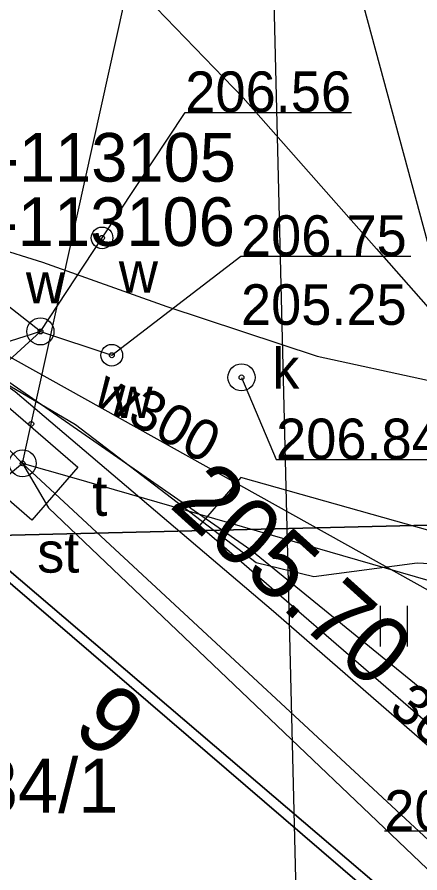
# Model space of a CAD drawing. Extents: x 6512606 to 6513347, y 6022524 to 6022728.
# Drawn here: x 6512803.1 to 6512810.55, y 6022664.12 to 6022679.94 of the extents above; entities that cross this region are included whole.
import ezdxf

# ---------------------------------------------------------------- set-up
doc = ezdxf.new("R2010")
doc.units = 0
for name, color, linetype in [('121-Punkt osnowy szczegółowej-Atr103', 7, 'Continuous'), ('211-numer działki ewidencyjnej', 7, 'Continuous'), ('216-obręb ewidencyjny', 7, 'Continuous'), ('217-kontur klasyfikacyjny', 7, 'Continuous'), ('218-kontur użytku gruntowego', 7, 'Continuous'), ('219-działka ewidencyjna', 7, 'Continuous'), ('238-Punkt adresowy budynku', 7, 'Continuous'), ('312-budynek ewidencyjny', 7, 'Continuous'), ('4', 7, 'Continuous'), ('940-Trawnik symb. poj.', 7, 'Continuous'), ('chodnik (powierzchnia)', 7, 'Continuous'), ('Default', 7, 'Continuous'), ('inna obudowa przewodu - sieć telekomunikacyjna (linia)', 7, 'Continuous'), ('komora podziemna - przewód telekomunikacyjny (powierzchnia)', 7, 'Continuous'), ('krawężnik (linia)', 7, 'Continuous'), ('Obszar opracowania', 7, 'Continuous'), ('przewód elektroenergetyczny (linia)', 7, 'Continuous'), ('przewód elektroenergetyczny (linia)-Atr1', 7, 'Continuous'), ('przewód kanalizacyjny (linia)', 7, 'Continuous'), ('przewód telekomunikacyjny (linia)', 7, 'Continuous'), ('przewód wodociągowy (linia)', 7, 'Continuous'), ('przewód wodociągowy (linia)-Atr1', 7, 'Continuous'), ('punkt o określonej wysokości (sieć kanalizacyjna)', 7, 'Continuous'), ('punkt o określonej wysokości (sieć kanalizacyjna)-Atr2', 7, 'Continuous'), ('punkt o określonej wysokości (sieć telekomunikacyjna)', 7, 'Continuous'), ('punkt o określonej wysokości (sieć telekomunikacyjna)-Atr2', 7, 'Continuous'), ('punkt o określonej wysokości (sieć wodociągowa)', 7, 'Continuous'), ('punkt o określonej wysokości (sieć wodociągowa)-Atr2', 7, 'Continuous'), ('punkt o określonej wysokości (sieć wodociągowa)-Atr3', 7, 'Continuous'), ('szafa telekomunikacyjna (punkt)-Atr17', 7, 'Continuous'), ('właz okrągły - siec kanalizacyjna (punkt)', 7, 'Continuous'), ('właz okrągły - siec kanalizacyjna (punkt)-Atr17', 7, 'Continuous'), ('właz okrągły - siec telekomunikacyjna (punkt)', 7, 'Continuous'), ('właz okrągły - siec telekomunikacyjna (punkt)-Atr17', 7, 'Continuous'), ('właz okrągły - siec wodociągowa (punkt)', 7, 'Continuous'), ('właz okrągły - siec wodociągowa (punkt)-Atr17', 7, 'Continuous'), ('zasuwa - siec wodociągowa (punkt)', 7, 'Continuous'), ('zasuwa - siec wodociągowa (punkt)-Atr17', 7, 'Continuous')]:
    doc.layers.add(name, color=color, linetype=linetype)

# ---------------------------------------------------------------- blocks, each defined once
blk = doc.blocks.new('940P')
at = {"layer": 'Default'}
for p, q in [((-2.5, -3.75), (-2.5, 3.75)), ((2.5, -3.75), (2.5, 3.75))]:
    blk.add_line(p, q, dxfattribs=at)
blk = doc.blocks.new('US22')
at = {"layer": 'Default'}
blk.add_circle((0, 0), 2.5, dxfattribs=at)
blk = doc.blocks.new('PW01')
at = {"layer": 'Default'}
blk.add_circle((0, 0), 0.45, dxfattribs=at)
blk = doc.blocks.new('US25')
at = {"layer": 'Default'}
blk.add_circle((0, 0), 2, dxfattribs=at)

msp = doc.modelspace()

# ---------------------------------------------------------------- linework, layer by layer
at = {"layer": '216-obręb ewidencyjny'}
for points in [[(6512688.62, 6022674.91), (6512702.58, 6022674.18), (6512725.78, 6022672.95), (6512730.35, 6022672.71), (6512735.76, 6022672.94), (6512745.51, 6022673.33), (6512754.87, 6022673.72), (6512768.24, 6022674.27), (6512785.56, 6022674.74), (6512790.49, 6022674.74), (6512796.96, 6022674.74), (6512801.96, 6022670.34), (6512828.67, 6022670.98), (6512833.61, 6022675.02), (6512836.69, 6022675.17), (6512851.94, 6022675.93)], [(6512836.687, 6022675.173), (6512833.61, 6022675.02), (6512828.67, 6022670.98), (6512801.96, 6022670.34), (6512810.18, 6022663.28), (6512825.37, 6022649.66), (6512838.47, 6022634.29), (6512852.25, 6022608.25), (6512853.17, 6022604.51), (6512855.78, 6022583.95), (6512858.85, 6022571.74), (6512828.23, 6022562.62), (6512818.47, 6022559.72), (6512824.714, 6022553.406)], [(6512852.25, 6022608.25), (6512838.47, 6022634.29), (6512825.37, 6022649.66), (6512810.18, 6022663.28), (6512801.96, 6022670.34), (6512796.96, 6022674.74), (6512790.49, 6022674.74), (6512785.56, 6022674.74), (6512768.24, 6022674.27), (6512754.87, 6022673.72), (6512745.51, 6022673.33), (6512735.76, 6022672.94), (6512730.35, 6022672.71), (6512725.78, 6022672.95), (6512702.575, 6022674.177)]]:
    msp.add_lwpolyline(points, dxfattribs=at)
at = {"layer": '217-kontur klasyfikacyjny'}
msp.add_lwpolyline([(6512810.18, 6022663.28), (6512801.96, 6022670.34)], dxfattribs=at)
at = {"layer": '218-kontur użytku gruntowego'}
for points in [[(6512801.96, 6022670.34), (6512828.67, 6022670.98)], [(6512828.67, 6022670.98), (6512801.96, 6022670.34)], [(6512810.18, 6022663.28), (6512801.96, 6022670.34)], [(6512801.96, 6022670.34), (6512810.18, 6022663.28)]]:
    msp.add_lwpolyline(points, dxfattribs=at)
at = {"layer": '219-działka ewidencyjna'}
for points in [[(6512828.67, 6022670.98), (6512801.96, 6022670.34)], [(6512801.96, 6022670.34), (6512810.18, 6022663.28)]]:
    msp.add_lwpolyline(points, dxfattribs=at)
at = {"layer": '312-budynek ewidencyjny'}
msp.add_lwpolyline([(6512802.06, 6022670.47), (6512810.3, 6022663.44)], dxfattribs=at)
at = {"layer": '4'}
for points in [[(6512828.67, 6022670.98), (6512801.96, 6022670.34)], [(6512801.96, 6022670.34), (6512810.18, 6022663.28)]]:
    msp.add_lwpolyline(points, dxfattribs=at)
at = {"layer": 'chodnik (powierzchnia)'}
for points in [[(6512845.61, 6022610.5), (6512844.69, 6022613.44), (6512844.06, 6022613.28), (6512843.41, 6022615.01), (6512844.01, 6022615.23), (6512838.87, 6022629.83), (6512839.52, 6022630.32), (6512838.94, 6022631.84), (6512838.15, 6022631.88), (6512837.86, 6022632.79), (6512838.13, 6022633.96), (6512826.89, 6022646.81), (6512825.11, 6022648.85), (6512824.32, 6022649.76), (6512820.29, 6022654.03), (6512817.62, 6022656.88), (6512816.1, 6022658.5), (6512810.3, 6022663.44), (6512802.06, 6022670.47), (6512797.05, 6022674.74)], [(6512830.64, 6022661.41), (6512827.95, 6022665.6), (6512807.24, 6022671.43), (6512806.47, 6022670.54), (6512810.75, 6022666.84), (6512818.47, 6022659.95), (6512819.77, 6022658.75), (6512822.35, 6022656.36), (6512823.62, 6022655.17), (6512828.35, 6022650.49), (6512830.32, 6022651.26)]]:
    msp.add_lwpolyline(points, dxfattribs=at)
at = {"layer": 'inna obudowa przewodu - sieć telekomunikacyjna (linia)'}
for points in [[(6512803.35, 6022672.37), (6512803.36, 6022672.42), (6512806.94, 6022688.62), (6512806.95, 6022688.66)], [(6512829.04, 6022664.23), (6512828.99, 6022664.24), (6512804.11, 6022671.43), (6512804.07, 6022671.44)]]:
    msp.add_lwpolyline(points, dxfattribs=at)
at = {"layer": 'komora podziemna - przewód telekomunikacyjny (powierzchnia)'}
msp.add_lwpolyline([(6512804.22, 6022671.62), (6512803.37, 6022670.64), (6512802.05, 6022671.78), (6512802.89, 6022672.77)], close=True, dxfattribs=at)
at = {"layer": 'krawężnik (linia)'}
msp.add_lwpolyline([(6512799.61, 6022676.46), (6512800.1, 6022676.4), (6512801.75, 6022675.98), (6512803.57, 6022675.41), (6512805.87, 6022674.59), (6512808.65, 6022673.67), (6512810.69, 6022673.23), (6512812.18, 6022673.12), (6512821.17, 6022672.6), (6512827.66, 6022672.22)], dxfattribs=at)
at = {"layer": 'Obszar opracowania'}
msp.add_lwpolyline([(6512710.98, 6022693.84), (6512748.35, 6022694.16), (6512798.11, 6022695.25), (6512807.47, 6022695.46), (6512809.66, 6022606.87), (6512863.71, 6022622.03), (6512875.13, 6022581.36), (6512755.22, 6022535.25), (6512691.61, 6022568.03), (6512709.16, 6022605.16)], close=True, dxfattribs=at)
at = {"layer": 'przewód elektroenergetyczny (linia)'}
for points in [[(6512702.569, 6022673.878), (6512710.28, 6022673.25), (6512716.66, 6022675.97), (6512746.13, 6022674.3), (6512752.79, 6022674.32), (6512760.61, 6022675.35), (6512763.38, 6022676.06), (6512798.79, 6022676.04), (6512803.06, 6022673.02), (6512807.84, 6022668.96), (6512815.24, 6022662.53), (6512819.98, 6022657.77), (6512831.6, 6022645.79), (6512834.59, 6022642.25), (6512837.06, 6022638.75), (6512840.02, 6022634.13), (6512842.26, 6022630.04), (6512846.03, 6022621.35), (6512846.58, 6022618.9), (6512847.6, 6022616.23), (6512852.12, 6022605.09)], [(6512776, 6022676.02), (6512799.41, 6022675.19), (6512801.88, 6022673.76), (6512804.18, 6022672.41), (6512807.52, 6022669.86), (6512808.59, 6022669.6), (6512810.5, 6022669.85), (6512831.73, 6022668.71)], [(6512802.27, 6022673.66), (6512807.42, 6022670.09), (6512811.38, 6022666.87), (6512814.66, 6022663.43), (6512826.4, 6022651.65), (6512827.82, 6022650.09), (6512834.03, 6022642.46), (6512842.84, 6022631.19), (6512844.67, 6022626.95), (6512847.57, 6022619.87), (6512849.81, 6022612.67), (6512853.56, 6022600.08), (6512856.46, 6022588.83), (6512861.26, 6022569.82), (6512861.768, 6022567.654)]]:
    msp.add_lwpolyline(points, dxfattribs=at)
at = {"layer": 'przewód kanalizacyjny (linia)'}
for points in [[(6512808.18, 6022685.05), (6512811.35, 6022673.34)], [(6512803.88, 6022681.97), (6512807.28, 6022678.45), (6512809.75, 6022675.66)], [(6512809.75, 6022675.66), (6512823.01, 6022660.61), (6512831.4, 6022651.41), (6512840.81, 6022640.51)]]:
    msp.add_lwpolyline(points, dxfattribs=at)
at = {"layer": 'przewód telekomunikacyjny (linia)'}
for points in [[(6512803.2, 6022671.69), (6512803.36, 6022672.42), (6512806.94, 6022688.62), (6512807.08, 6022689.26)], [(6512803.2, 6022671.69), (6512802.51, 6022672.39), (6512787.26, 6022687.76), (6512786.53, 6022688.5)], [(6512829.92, 6022664.12), (6512829.04, 6022664.23), (6512828.99, 6022664.24), (6512804.11, 6022671.43), (6512803.2, 6022671.69)], [(6512803.2, 6022671.69), (6512803.68, 6022670.87), (6512814.12, 6022660.92), (6512820.62, 6022654.75), (6512822.04, 6022653.36), (6512827.37, 6022648.58), (6512829.25, 6022646.9)], [(6512829.25, 6022646.9), (6512828.69, 6022647.83), (6512819.07, 6022656.76), (6512812.33, 6022663.22), (6512803.2, 6022671.69)]]:
    msp.add_lwpolyline(points, dxfattribs=at)
at = {"layer": 'przewód wodociągowy (linia)'}
for points in [[(6512776.98, 6022676.45), (6512777.41, 6022676.47), (6512777.83, 6022676.47), (6512787.32, 6022676), (6512787.61, 6022675.99), (6512796.6, 6022675.55), (6512799.85, 6022675.39), (6512814.29, 6022667.35), (6512815.22, 6022667.12), (6512815.2, 6022666.73), (6512814.74, 6022665.5)], [(6512803.53, 6022674.13), (6512802.06, 6022675.28), (6512802.33, 6022676.21)], [(6512803.53, 6022674.13), (6512804.67, 6022675.86)], [(6512803.53, 6022674.13), (6512800.75, 6022671.59)], [(6512803.53, 6022674.13), (6512804.85, 6022673.69)]]:
    msp.add_lwpolyline(points, dxfattribs=at)
at = {"layer": 'punkt o określonej wysokości (sieć kanalizacyjna)-Atr2'}
for points in [[(6512807.25, 6022673.28), (6512807.89, 6022671.76), (6512811.031, 6022671.76)], [(6512813.97, 6022666.12), (6512812.97, 6022664.89), (6512809.893, 6022664.89)]]:
    msp.add_lwpolyline(points, dxfattribs=at)
at = {"layer": 'punkt o określonej wysokości (sieć telekomunikacyjna)-Atr2'}
msp.add_lwpolyline([(6512803.2, 6022671.69), (6512800.87, 6022669.76), (6512797.729, 6022669.76)], dxfattribs=at)
at = {"layer": 'punkt o określonej wysokości (sieć wodociągowa)-Atr2'}
for points in [[(6512804.67, 6022675.86), (6512806.21, 6022678.18), (6512809.287, 6022678.18)], [(6512804.85, 6022673.69), (6512807.24, 6022675.52), (6512810.381, 6022675.52)], [(6512803.53, 6022674.13), (6512798.79, 6022672.62), (6512795.617, 6022672.62)]]:
    msp.add_lwpolyline(points, dxfattribs=at)

# ---------------------------------------------------------------- block references
at = {"layer": '940-Trawnik symb. poj.', "xscale": 0.1, "yscale": 0.10000000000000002}
msp.add_blockref('940P', (6512810.07, 6022668.68), dxfattribs=at)
at = {"layer": 'punkt o określonej wysokości (sieć kanalizacyjna)', "xscale": 0.1, "yscale": 0.10000000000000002}
msp.add_blockref('PW01', (6512807.25, 6022673.28), dxfattribs=at)
at = {"layer": 'punkt o określonej wysokości (sieć telekomunikacyjna)', "xscale": 0.1, "yscale": 0.10000000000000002}
for p, rotation in [((6512803.36, 6022672.42), 78.328), ((6512803.2, 6022671.69), -43.02000000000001)]:
    msp.add_blockref('PW01', p, dxfattribs=dict(at, rotation=rotation))
at = {"layer": 'punkt o określonej wysokości (sieć wodociągowa)', "xscale": 0.09999999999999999}
for p, yscale, rotation in [((6512804.67, 6022675.86), 0.1, 57.614), ((6512804.85, 6022673.69), 0.10000000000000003, -32.218)]:
    msp.add_blockref('PW01', p, dxfattribs=dict(at, yscale=yscale, rotation=rotation))
at = {"layer": 'punkt o określonej wysokości (sieć wodociągowa)', "xscale": 0.1, "yscale": 0.10000000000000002}
msp.add_blockref('PW01', (6512803.53, 6022674.13), dxfattribs=at)
at = {"layer": 'właz okrągły - siec kanalizacyjna (punkt)', "xscale": 0.1, "yscale": 0.10000000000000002}
msp.add_blockref('US22', (6512807.25, 6022673.28), dxfattribs=at)
at = {"layer": 'właz okrągły - siec telekomunikacyjna (punkt)', "xscale": 0.1, "yscale": 0.10000000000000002, "rotation": -43.02000000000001}
msp.add_blockref('US22', (6512803.2, 6022671.69), dxfattribs=at)
at = {"layer": 'właz okrągły - siec wodociągowa (punkt)', "xscale": 0.1, "yscale": 0.10000000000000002}
msp.add_blockref('US22', (6512803.53, 6022674.13), dxfattribs=at)
at = {"layer": 'zasuwa - siec wodociągowa (punkt)', "xscale": 0.09999999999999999}
for p, yscale, rotation in [((6512804.67, 6022675.86), 0.1, 57.614), ((6512804.85, 6022673.69), 0.10000000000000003, -32.218)]:
    msp.add_blockref('US25', p, dxfattribs=dict(at, yscale=yscale, rotation=rotation))

# ---------------------------------------------------------------- texts
at = {"layer": '121-Punkt osnowy szczegółowej-Atr103'}
for s, p in [('314.444-113105', (6512798.38, 6022676.9)), ('314.444-113106', (6512798.36, 6022675.71))]:
    msp.add_text(s, height=0.9, dxfattribs=at).set_placement(p)
at = {"layer": '211-numer działki ewidencyjnej'}
msp.add_text('34/1', height=1, dxfattribs=at).set_placement((6512802.37, 6022665.23))
at = {"layer": '238-Punkt adresowy budynku'}
msp.add_text('6', height=1.25, rotation=140.357, dxfattribs=at).set_placement((6512805.6, 6022667.12))
at = {"layer": '4'}
msp.add_text('34/1', height=1, dxfattribs=at).set_placement((6512802.37, 6022665.23))
at = {"layer": 'przewód elektroenergetyczny (linia)-Atr1'}
msp.add_text('3eW', height=0.75, rotation=319.843, dxfattribs=at).set_placement((6512809.95, 6022667.12))
at = {"layer": 'przewód wodociągowy (linia)-Atr1'}
msp.add_text('w300', height=0.75, rotation=331.683, dxfattribs=at).set_placement((6512804.47, 6022672.81))
at = {"layer": 'punkt o określonej wysokości (sieć kanalizacyjna)-Atr2'}
for s, p in [('206.84', (6512807.89, 6022671.768)), ('206.68', (6512809.893, 6022664.897))]:
    msp.add_text(s, height=0.75, dxfattribs=at).set_placement(p)
at = {"layer": 'punkt o określonej wysokości (sieć telekomunikacyjna)'}
msp.add_text('205.70', height=1.25, rotation=317.962, dxfattribs=at).set_placement((6512805.89, 6022670.9))
at = {"layer": 'punkt o określonej wysokości (sieć wodociągowa)-Atr2'}
for s, p in [('206.56', (6512806.21, 6022678.188)), ('206.75', (6512807.24, 6022675.527))]:
    msp.add_text(s, height=0.75, dxfattribs=at).set_placement(p)
at = {"layer": 'punkt o określonej wysokości (sieć wodociągowa)-Atr3'}
msp.add_text('205.25', height=0.75, dxfattribs=at).set_placement((6512807.24, 6022674.252))
at = {"layer": 'szafa telekomunikacyjna (punkt)-Atr17'}
msp.add_text('st', height=0.75, dxfattribs=at).set_placement((6512803.47, 6022669.67))
at = {"layer": 'właz okrągły - siec kanalizacyjna (punkt)-Atr17'}
msp.add_text('k', height=0.75, dxfattribs=at).set_placement((6512807.82, 6022673.07))
at = {"layer": 'właz okrągły - siec telekomunikacyjna (punkt)-Atr17'}
msp.add_text('t', height=0.75, dxfattribs=at).set_placement((6512804.49, 6022670.72))
at = {"layer": 'właz okrągły - siec wodociągowa (punkt)-Atr17'}
msp.add_text('w', height=0.75, dxfattribs=at).set_placement((6512803.26, 6022674.65))
at = {"layer": 'zasuwa - siec wodociągowa (punkt)-Atr17'}
for p in [(6512804.98, 6022674.85), (6512804.88, 6022672.53)]:
    msp.add_text('w', height=0.75, dxfattribs=at).set_placement(p)

doc.saveas('drawing.dxf')
